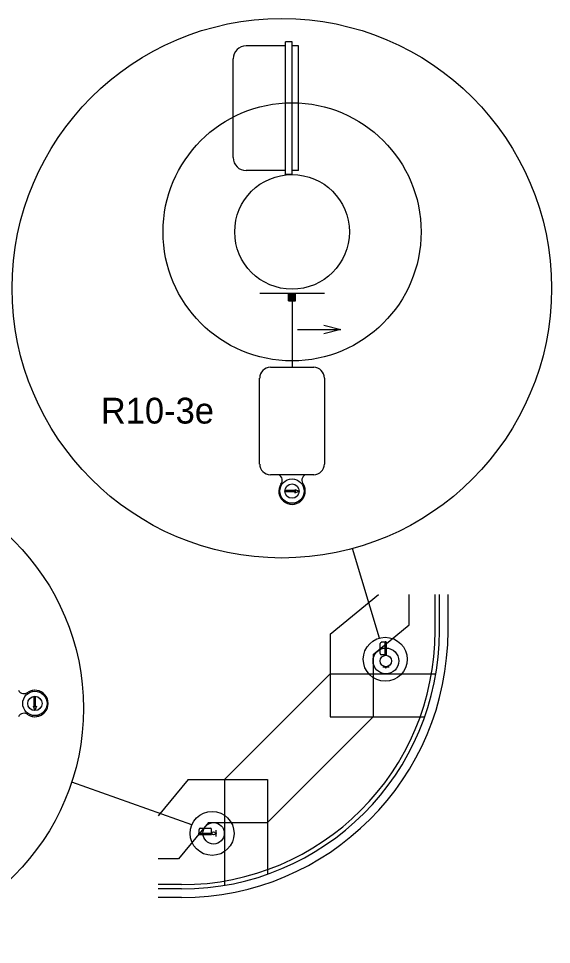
# Model space of a CAD drawing. Extents: x 418532 to 420296, y -565948 to -565286.
# Drawn here: x 419692.3 to 419785.2, y -565790.4 to -565629 of the extents above; entities that cross this region are included whole.
import ezdxf

# ---------------------------------------------------------------- set-up
doc = ezdxf.new("R2010")
doc.units = 0
doc.layers.add('T_Drafting', color=7, linetype='Continuous')

msp = doc.modelspace()

# ---------------------------------------------------------------- linework, layer by layer
at = {"layer": 'T_Drafting'}
for p, q in [((419738.87, -565656.2), (419738.87, -565633.07)), ((419739.99, -565633.07), (419738.87, -565633.07)), ((419739.99, -565656.2), (419739.99, -565633.07)), ((419738.87, -565633.76), (419731.99, -565633.76)), ((419741.12, -565633.76), (419739.99, -565633.76)), ((419741.12, -565655.51), (419741.12, -565633.76)), ((419729.74, -565653.26), (419729.74, -565636.01)), ((419738.87, -565655.51), (419731.99, -565655.51)), ((419741.12, -565655.51), (419739.99, -565655.51)), ((419739.99, -565656.2), (419738.87, -565656.2)), ((419745.62, -565676.95), (419734.37, -565676.95)), ((419739.37, -565678.2), (419739.37, -565676.95)), ((419739.37, -565678.19), (419740.61, -565676.95)), ((419739.37, -565678.17), (419740.59, -565676.95)), ((419739.37, -565678.14), (419740.57, -565676.95)), ((419739.37, -565678.12), (419740.55, -565676.95)), ((419739.37, -565678.1), (419740.52, -565676.95)), ((419739.37, -565678.08), (419740.5, -565676.95)), ((419739.37, -565678.06), (419740.48, -565676.95)), ((419739.37, -565678.04), (419740.46, -565676.95)), ((419739.37, -565678.02), (419740.44, -565676.95)), ((419739.37, -565678), (419740.42, -565676.95)), ((419739.37, -565677.98), (419740.4, -565676.95)), ((419739.37, -565677.95), (419740.38, -565676.95)), ((419739.37, -565677.93), (419740.35, -565676.95)), ((419739.37, -565677.91), (419740.33, -565676.95)), ((419739.37, -565677.89), (419740.31, -565676.95)), ((419739.37, -565677.87), (419740.29, -565676.95)), ((419739.37, -565677.85), (419740.27, -565676.95)), ((419739.37, -565677.83), (419740.25, -565676.95)), ((419739.37, -565677.81), (419740.23, -565676.95)), ((419739.37, -565677.78), (419740.21, -565676.95)), ((419739.37, -565677.76), (419740.19, -565676.95)), ((419739.37, -565677.74), (419740.16, -565676.95)), ((419739.37, -565677.72), (419740.14, -565676.95)), ((419739.37, -565677.7), (419740.12, -565676.95)), ((419739.37, -565677.68), (419740.1, -565676.95)), ((419739.37, -565677.66), (419740.08, -565676.95)), ((419739.37, -565677.64), (419740.06, -565676.95)), ((419739.37, -565677.61), (419740.04, -565676.95)), ((419739.37, -565677.59), (419740.02, -565676.95)), ((419739.37, -565677.57), (419739.99, -565676.95)), ((419739.37, -565677.55), (419739.97, -565676.95)), ((419739.37, -565677.53), (419739.95, -565676.95)), ((419739.37, -565677.51), (419739.93, -565676.95)), ((419739.37, -565677.49), (419739.91, -565676.95)), ((419739.37, -565677.47), (419739.89, -565676.95)), ((419739.37, -565677.44), (419739.87, -565676.95)), ((419739.37, -565677.42), (419739.85, -565676.95)), ((419739.37, -565677.4), (419739.82, -565676.95)), ((419739.37, -565677.38), (419739.8, -565676.95)), ((419739.37, -565677.36), (419739.78, -565676.95)), ((419739.37, -565677.34), (419739.76, -565676.95)), ((419739.37, -565677.32), (419739.74, -565676.95)), ((419739.37, -565677.3), (419739.72, -565676.95)), ((419739.37, -565677.28), (419739.7, -565676.95)), ((419739.37, -565677.25), (419739.68, -565676.95)), ((419739.37, -565677.23), (419739.65, -565676.95)), ((419739.37, -565677.21), (419739.63, -565676.95)), ((419739.37, -565677.19), (419739.61, -565676.95)), ((419739.37, -565677.17), (419739.59, -565676.95)), ((419739.37, -565677.15), (419739.57, -565676.95)), ((419739.37, -565677.13), (419739.55, -565676.95)), ((419739.37, -565677.11), (419739.53, -565676.95)), ((419739.37, -565677.08), (419739.51, -565676.95)), ((419739.37, -565677.06), (419739.49, -565676.95)), ((419739.37, -565677.04), (419739.46, -565676.95)), ((419739.37, -565677.02), (419739.44, -565676.95)), ((419739.37, -565677), (419739.42, -565676.95)), ((419739.37, -565676.98), (419739.4, -565676.95)), ((419739.37, -565676.96), (419739.38, -565676.95)), ((419739.38, -565678.2), (419740.62, -565676.96)), ((419739.4, -565678.2), (419740.62, -565676.98)), ((419739.42, -565678.2), (419740.62, -565677)), ((419739.44, -565678.2), (419740.62, -565677.02)), ((419739.47, -565678.2), (419740.62, -565677.04)), ((419739.49, -565678.2), (419740.62, -565677.06)), ((419739.51, -565678.2), (419740.62, -565677.09)), ((419739.53, -565678.2), (419740.62, -565677.11)), ((419739.55, -565678.2), (419740.62, -565677.13)), ((419740.62, -565678.2), (419740.62, -565676.95)), ((419739.37, -565678.2), (419740.62, -565678.2)), ((419739.57, -565678.2), (419740.62, -565677.15)), ((419739.59, -565678.2), (419740.62, -565677.17)), ((419739.61, -565678.2), (419740.62, -565677.19)), ((419739.64, -565678.2), (419740.62, -565677.21)), ((419739.66, -565678.2), (419740.62, -565677.23)), ((419739.68, -565678.2), (419740.62, -565677.26)), ((419739.7, -565678.2), (419740.62, -565677.28)), ((419739.72, -565678.2), (419740.62, -565677.3)), ((419739.74, -565678.2), (419740.62, -565677.32)), ((419739.76, -565678.2), (419740.62, -565677.34)), ((419739.78, -565678.2), (419740.62, -565677.36)), ((419739.8, -565678.2), (419740.62, -565677.38)), ((419739.83, -565678.2), (419740.62, -565677.4)), ((419739.85, -565678.2), (419740.62, -565677.43)), ((419739.87, -565678.2), (419740.62, -565677.45)), ((419739.89, -565678.2), (419740.62, -565677.47)), ((419739.91, -565678.2), (419740.62, -565677.49)), ((419739.93, -565678.2), (419740.62, -565677.51)), ((419739.95, -565678.2), (419740.62, -565677.53)), ((419739.97, -565678.2), (419740.62, -565677.55)), ((419739.99, -565678.2), (419739.99, -565689.8)), ((419740, -565678.2), (419740.62, -565677.57)), ((419740.02, -565678.2), (419740.62, -565677.59)), ((419740.04, -565678.2), (419740.62, -565677.62)), ((419740.06, -565678.2), (419740.62, -565677.64)), ((419740.08, -565678.2), (419740.62, -565677.66)), ((419740.1, -565678.2), (419740.62, -565677.68)), ((419740.12, -565678.2), (419740.62, -565677.7)), ((419740.14, -565678.2), (419740.62, -565677.72)), ((419740.17, -565678.2), (419740.62, -565677.74)), ((419740.19, -565678.2), (419740.62, -565677.76)), ((419740.21, -565678.2), (419740.62, -565677.79)), ((419740.23, -565678.2), (419740.62, -565677.81)), ((419740.25, -565678.2), (419740.62, -565677.83)), ((419740.27, -565678.2), (419740.62, -565677.85)), ((419740.29, -565678.2), (419740.62, -565677.87)), ((419740.31, -565678.2), (419740.62, -565677.89)), ((419740.34, -565678.2), (419740.62, -565677.91)), ((419740.36, -565678.2), (419740.62, -565677.93)), ((419740.38, -565678.2), (419740.62, -565677.96)), ((419740.4, -565678.2), (419740.62, -565677.98)), ((419740.42, -565678.2), (419740.62, -565678)), ((419740.44, -565678.2), (419740.62, -565678.02)), ((419740.46, -565678.2), (419740.62, -565678.04)), ((419740.48, -565678.2), (419740.62, -565678.06)), ((419740.5, -565678.2), (419740.62, -565678.08)), ((419740.53, -565678.2), (419740.62, -565678.1)), ((419740.55, -565678.2), (419740.62, -565678.13)), ((419740.57, -565678.2), (419740.62, -565678.15)), ((419740.59, -565678.2), (419740.62, -565678.17)), ((419740.61, -565678.2), (419740.62, -565678.19)), ((419740.96, -565683.2), (419748.51, -565683.2)), ((419736.22, -565689.8), (419743.77, -565689.8)), ((419734.34, -565706.68), (419734.34, -565691.68)), ((419745.64, -565691.68), (419745.64, -565706.68)), ((419743.77, -565708.55), (419736.22, -565708.55)), ((419738.75, -565711.29), (419738.75, -565711.51)), ((419740.63, -565711.29), (419738.75, -565711.29)), ((419740.63, -565711.51), (419738.75, -565711.51)), ((419740.48, -565711.1), (419741.24, -565711.4)), ((419740.63, -565711.29), (419740.48, -565711.1)), ((419740.48, -565711.7), (419741.24, -565711.4)), ((419740.48, -565711.7), (419740.63, -565711.51)), ((419755.22, -565737.02), (419750.51, -565721.42)), ((419746.61, -565736.36), (419755.07, -565729.41)), ((419760.44, -565734.71), (419760.44, -565729.41)), ((419764.94, -565735.76), (419764.94, -565729.41)), ((419765.69, -565735.76), (419765.69, -565729.41)), ((419767.19, -565735.76), (419767.19, -565729.41)), ((419754.11, -565739.91), (419760.44, -565734.71)), ((419746.61, -565736.36), (419746.61, -565750.76)), ((419755.34, -565739.71), (419755.34, -565737.99)), ((419756.25, -565737.76), (419755.56, -565737.76)), ((419756.25, -565740.01), (419756.25, -565737.69)), ((419756.36, -565737.69), (419756.25, -565737.69)), ((419756.36, -565740.01), (419756.36, -565737.69)), ((419756.48, -565737.76), (419756.36, -565737.76)), ((419756.48, -565739.94), (419756.48, -565737.76)), ((419754.11, -565739.91), (419754.11, -565750.76)), ((419756.25, -565739.94), (419755.56, -565739.94)), ((419756.36, -565740.01), (419756.25, -565740.01)), ((419756.48, -565739.94), (419756.36, -565739.94)), ((419746.61, -565743.26), (419728.19, -565761.68)), ((419746.61, -565743.26), (419765.06, -565743.26)), ((419756.93, -565742.08), (419755.8, -565742.08)), ((419756.3, -565742.21), (419756.3, -565742.08)), ((419756.3, -565742.21), (419756.43, -565742.08)), ((419756.3, -565742.21), (419756.43, -565742.08)), ((419756.3, -565742.2), (419756.43, -565742.08)), ((419756.3, -565742.2), (419756.42, -565742.08)), ((419756.3, -565742.2), (419756.42, -565742.08)), ((419756.3, -565742.2), (419756.42, -565742.08)), ((419756.3, -565742.2), (419756.42, -565742.08)), ((419756.3, -565742.19), (419756.41, -565742.08)), ((419756.3, -565742.19), (419756.41, -565742.08)), ((419756.3, -565742.19), (419756.41, -565742.08)), ((419756.3, -565742.19), (419756.41, -565742.08)), ((419756.3, -565742.19), (419756.41, -565742.08)), ((419756.3, -565742.18), (419756.4, -565742.08)), ((419756.3, -565742.18), (419756.4, -565742.08)), ((419756.3, -565742.18), (419756.4, -565742.08)), ((419756.3, -565742.18), (419756.4, -565742.08)), ((419756.3, -565742.17), (419756.4, -565742.08)), ((419756.3, -565742.17), (419756.39, -565742.08)), ((419756.3, -565742.17), (419756.39, -565742.08)), ((419756.3, -565742.17), (419756.39, -565742.08)), ((419756.3, -565742.17), (419756.39, -565742.08)), ((419756.3, -565742.16), (419756.39, -565742.08)), ((419756.3, -565742.16), (419756.38, -565742.08)), ((419756.3, -565742.16), (419756.38, -565742.08)), ((419756.3, -565742.16), (419756.38, -565742.08)), ((419756.3, -565742.16), (419756.38, -565742.08)), ((419756.3, -565742.15), (419756.37, -565742.08)), ((419756.3, -565742.15), (419756.37, -565742.08)), ((419756.3, -565742.15), (419756.37, -565742.08)), ((419756.3, -565742.15), (419756.37, -565742.08)), ((419756.3, -565742.14), (419756.37, -565742.08)), ((419756.3, -565742.14), (419756.36, -565742.08)), ((419756.3, -565742.14), (419756.36, -565742.08)), ((419756.3, -565742.14), (419756.36, -565742.08)), ((419756.3, -565742.14), (419756.36, -565742.08)), ((419756.3, -565742.13), (419756.36, -565742.08)), ((419756.3, -565742.13), (419756.35, -565742.08)), ((419756.3, -565742.13), (419756.35, -565742.08)), ((419756.3, -565742.13), (419756.35, -565742.08)), ((419756.3, -565742.13), (419756.35, -565742.08)), ((419756.3, -565742.12), (419756.34, -565742.08)), ((419756.3, -565742.12), (419756.34, -565742.08)), ((419756.3, -565742.12), (419756.34, -565742.08)), ((419756.3, -565742.12), (419756.34, -565742.08)), ((419756.3, -565742.12), (419756.34, -565742.08)), ((419756.3, -565742.11), (419756.33, -565742.08)), ((419756.3, -565742.11), (419756.33, -565742.08)), ((419756.3, -565742.11), (419756.33, -565742.08)), ((419756.3, -565742.11), (419756.33, -565742.08)), ((419756.3, -565742.1), (419756.33, -565742.08)), ((419756.3, -565742.1), (419756.32, -565742.08)), ((419756.3, -565742.1), (419756.32, -565742.08)), ((419756.3, -565742.1), (419756.32, -565742.08)), ((419756.3, -565742.1), (419756.32, -565742.08)), ((419756.3, -565742.09), (419756.32, -565742.08)), ((419756.3, -565742.09), (419756.31, -565742.08)), ((419756.3, -565742.09), (419756.31, -565742.08)), ((419756.3, -565742.09), (419756.31, -565742.08)), ((419756.3, -565742.09), (419756.31, -565742.08)), ((419756.3, -565742.08), (419756.3, -565742.08)), ((419756.3, -565742.08), (419756.3, -565742.08)), ((419756.3, -565742.21), (419756.43, -565742.21)), ((419756.31, -565742.21), (419756.43, -565742.09)), ((419756.31, -565742.21), (419756.43, -565742.09)), ((419756.31, -565742.21), (419756.43, -565742.09)), ((419756.31, -565742.21), (419756.43, -565742.09)), ((419756.32, -565742.21), (419756.43, -565742.09)), ((419756.32, -565742.21), (419756.43, -565742.1)), ((419756.32, -565742.21), (419756.43, -565742.1)), ((419756.32, -565742.21), (419756.43, -565742.1)), ((419756.32, -565742.21), (419756.43, -565742.1)), ((419756.33, -565742.21), (419756.43, -565742.1)), ((419756.33, -565742.21), (419756.43, -565742.11)), ((419756.33, -565742.21), (419756.43, -565742.11)), ((419756.33, -565742.21), (419756.43, -565742.11)), ((419756.33, -565742.21), (419756.43, -565742.11)), ((419756.34, -565742.21), (419756.43, -565742.12)), ((419756.34, -565742.21), (419756.43, -565742.12)), ((419756.34, -565742.21), (419756.43, -565742.12)), ((419756.34, -565742.21), (419756.43, -565742.12)), ((419756.35, -565742.21), (419756.43, -565742.12)), ((419756.35, -565742.21), (419756.43, -565742.13)), ((419756.35, -565742.21), (419756.43, -565742.13)), ((419756.35, -565742.21), (419756.43, -565742.13)), ((419756.35, -565742.21), (419756.43, -565742.13)), ((419756.36, -565742.21), (419756.43, -565742.13)), ((419756.36, -565742.21), (419756.43, -565742.14)), ((419756.36, -565742.21), (419756.43, -565742.14)), ((419756.36, -565742.21), (419756.43, -565742.14)), ((419756.36, -565742.21), (419756.43, -565742.14)), ((419756.37, -565742.21), (419756.43, -565742.14)), ((419756.37, -565742.21), (419756.43, -565742.15)), ((419756.37, -565742.21), (419756.43, -565742.15)), ((419756.37, -565742.21), (419756.43, -565742.15)), ((419756.37, -565742.21), (419756.43, -565742.15)), ((419756.38, -565742.21), (419756.43, -565742.16)), ((419756.38, -565742.21), (419756.43, -565742.16)), ((419756.38, -565742.21), (419756.43, -565742.16)), ((419756.38, -565742.21), (419756.43, -565742.16)), ((419756.39, -565742.21), (419756.43, -565742.16)), ((419756.39, -565742.21), (419756.43, -565742.17)), ((419756.39, -565742.21), (419756.43, -565742.17)), ((419756.39, -565742.21), (419756.43, -565742.17)), ((419756.39, -565742.21), (419756.43, -565742.17)), ((419756.4, -565742.21), (419756.43, -565742.17)), ((419756.4, -565742.21), (419756.43, -565742.18)), ((419756.4, -565742.21), (419756.43, -565742.18)), ((419756.4, -565742.21), (419756.43, -565742.18)), ((419756.4, -565742.21), (419756.43, -565742.18)), ((419756.41, -565742.21), (419756.43, -565742.19)), ((419756.41, -565742.21), (419756.43, -565742.19)), ((419756.41, -565742.21), (419756.43, -565742.19)), ((419756.41, -565742.21), (419756.43, -565742.19)), ((419756.42, -565742.21), (419756.43, -565742.19)), ((419756.42, -565742.21), (419756.43, -565742.2)), ((419756.42, -565742.21), (419756.43, -565742.2)), ((419756.42, -565742.21), (419756.43, -565742.2)), ((419756.42, -565742.21), (419756.43, -565742.2)), ((419756.43, -565742.21), (419756.43, -565742.08)), ((419756.43, -565742.21), (419756.43, -565742.2)), ((419695.02, -565747.18), (419695.25, -565747.18)), ((419695.02, -565749.06), (419695.02, -565747.18)), ((419695.25, -565749.06), (419695.25, -565747.18)), ((419694.84, -565748.91), (419695.14, -565749.67)), ((419695.02, -565749.06), (419694.84, -565748.91)), ((419695.44, -565748.91), (419695.14, -565749.67)), ((419695.44, -565748.91), (419695.25, -565749.06)), ((419754.11, -565750.76), (419735.69, -565769.18)), ((419746.61, -565750.76), (419763.11, -565750.76)), ((419722.52, -565769.61), (419701.56, -565762.14)), ((419721.85, -565761.68), (419716.65, -565768.01)), ((419721.85, -565761.68), (419735.69, -565761.68)), ((419728.19, -565761.68), (419728.19, -565780.13)), ((419735.69, -565761.68), (419735.69, -565778.18)), ((419725.39, -565769.18), (419720.19, -565775.51)), ((419723.79, -565771.06), (419723.79, -565770.37)), ((419724.01, -565770.14), (419725.74, -565770.14)), ((419725.39, -565769.18), (419735.69, -565769.18)), ((419725.96, -565771.06), (419725.96, -565770.37)), ((419726.67, -565770.49), (419726.67, -565771.62)), ((419723.72, -565771.06), (419726.03, -565771.06)), ((419723.72, -565771.17), (419723.72, -565771.06)), ((419723.72, -565771.17), (419726.03, -565771.17)), ((419723.79, -565771.28), (419723.79, -565771.17)), ((419723.79, -565771.28), (419725.96, -565771.28)), ((419725.96, -565771.28), (419725.96, -565771.17)), ((419726.03, -565771.17), (419726.03, -565771.06)), ((419726.79, -565770.99), (419726.67, -565770.99)), ((419726.67, -565771.12), (419726.79, -565770.99)), ((419726.67, -565771.12), (419726.79, -565770.99)), ((419726.67, -565771.11), (419726.79, -565770.99)), ((419726.67, -565771.11), (419726.79, -565770.99)), ((419726.67, -565771.11), (419726.78, -565770.99)), ((419726.67, -565771.11), (419726.78, -565770.99)), ((419726.67, -565771.11), (419726.78, -565770.99)), ((419726.67, -565771.1), (419726.78, -565770.99)), ((419726.67, -565771.1), (419726.78, -565770.99)), ((419726.67, -565771.1), (419726.77, -565770.99)), ((419726.67, -565771.1), (419726.77, -565770.99)), ((419726.67, -565771.1), (419726.77, -565770.99)), ((419726.67, -565771.09), (419726.77, -565770.99)), ((419726.67, -565771.09), (419726.77, -565770.99)), ((419726.67, -565771.09), (419726.76, -565770.99)), ((419726.67, -565771.09), (419726.76, -565770.99)), ((419726.67, -565771.08), (419726.76, -565770.99)), ((419726.67, -565771.08), (419726.76, -565770.99)), ((419726.67, -565771.08), (419726.76, -565770.99)), ((419726.67, -565771.08), (419726.75, -565770.99)), ((419726.67, -565771.08), (419726.75, -565770.99)), ((419726.67, -565771.07), (419726.75, -565770.99)), ((419726.67, -565771.07), (419726.75, -565770.99)), ((419726.67, -565771.07), (419726.74, -565770.99)), ((419726.67, -565771.07), (419726.74, -565770.99)), ((419726.67, -565771.07), (419726.74, -565770.99)), ((419726.67, -565771.06), (419726.74, -565770.99)), ((419726.67, -565771.06), (419726.74, -565770.99)), ((419726.67, -565771.06), (419726.73, -565770.99)), ((419726.67, -565771.06), (419726.73, -565770.99)), ((419726.67, -565771.05), (419726.73, -565770.99)), ((419726.67, -565771.05), (419726.73, -565770.99)), ((419726.67, -565771.05), (419726.73, -565770.99)), ((419726.67, -565771.05), (419726.72, -565770.99)), ((419726.67, -565771.05), (419726.72, -565770.99)), ((419726.67, -565771.04), (419726.72, -565770.99)), ((419726.67, -565771.04), (419726.72, -565770.99)), ((419726.67, -565771.04), (419726.71, -565770.99)), ((419726.67, -565771.04), (419726.71, -565770.99)), ((419726.67, -565771.04), (419726.71, -565770.99)), ((419726.67, -565771.03), (419726.71, -565770.99)), ((419726.67, -565771.03), (419726.71, -565770.99)), ((419726.67, -565771.03), (419726.7, -565770.99)), ((419726.67, -565771.03), (419726.7, -565770.99)), ((419726.67, -565771.03), (419726.7, -565770.99)), ((419726.67, -565771.02), (419726.7, -565770.99)), ((419726.67, -565771.02), (419726.7, -565770.99)), ((419726.67, -565771.02), (419726.69, -565770.99)), ((419726.67, -565771.02), (419726.69, -565770.99)), ((419726.67, -565771.01), (419726.69, -565770.99)), ((419726.67, -565771.01), (419726.69, -565770.99)), ((419726.67, -565771.01), (419726.69, -565770.99)), ((419726.67, -565771.01), (419726.68, -565770.99)), ((419726.67, -565771.01), (419726.68, -565770.99)), ((419726.67, -565771), (419726.68, -565770.99)), ((419726.67, -565771), (419726.68, -565770.99)), ((419726.67, -565771), (419726.67, -565770.99)), ((419726.67, -565771), (419726.67, -565770.99)), ((419726.67, -565771), (419726.67, -565770.99)), ((419726.67, -565771.12), (419726.79, -565771)), ((419726.67, -565771.12), (419726.79, -565771)), ((419726.67, -565771.12), (419726.79, -565771)), ((419726.79, -565771.12), (419726.67, -565771.12)), ((419726.68, -565771.12), (419726.79, -565771)), ((419726.68, -565771.12), (419726.79, -565771)), ((419726.68, -565771.12), (419726.79, -565771.01)), ((419726.68, -565771.12), (419726.79, -565771.01)), ((419726.69, -565771.12), (419726.79, -565771.01)), ((419726.69, -565771.12), (419726.79, -565771.01)), ((419726.69, -565771.12), (419726.79, -565771.01)), ((419726.69, -565771.12), (419726.79, -565771.02)), ((419726.69, -565771.12), (419726.79, -565771.02)), ((419726.7, -565771.12), (419726.79, -565771.02)), ((419726.7, -565771.12), (419726.79, -565771.02)), ((419726.7, -565771.12), (419726.79, -565771.03)), ((419726.7, -565771.12), (419726.79, -565771.03)), ((419726.7, -565771.12), (419726.79, -565771.03)), ((419726.71, -565771.12), (419726.79, -565771.03)), ((419726.71, -565771.12), (419726.79, -565771.03)), ((419726.71, -565771.12), (419726.79, -565771.04)), ((419726.71, -565771.12), (419726.79, -565771.04)), ((419726.72, -565771.12), (419726.79, -565771.04)), ((419726.72, -565771.12), (419726.79, -565771.04)), ((419726.72, -565771.12), (419726.79, -565771.04)), ((419726.72, -565771.12), (419726.79, -565771.05)), ((419726.72, -565771.12), (419726.79, -565771.05)), ((419726.73, -565771.12), (419726.79, -565771.05)), ((419726.73, -565771.12), (419726.79, -565771.05)), ((419726.73, -565771.12), (419726.79, -565771.06)), ((419726.73, -565771.12), (419726.79, -565771.06)), ((419726.73, -565771.12), (419726.79, -565771.06)), ((419726.74, -565771.12), (419726.79, -565771.06)), ((419726.74, -565771.12), (419726.79, -565771.06)), ((419726.74, -565771.12), (419726.79, -565771.07)), ((419726.74, -565771.12), (419726.79, -565771.07)), ((419726.74, -565771.12), (419726.79, -565771.07)), ((419726.75, -565771.12), (419726.79, -565771.07)), ((419726.75, -565771.12), (419726.79, -565771.07)), ((419726.75, -565771.12), (419726.79, -565771.08)), ((419726.75, -565771.12), (419726.79, -565771.08)), ((419726.76, -565771.12), (419726.79, -565771.08)), ((419726.76, -565771.12), (419726.79, -565771.08)), ((419726.76, -565771.12), (419726.79, -565771.08)), ((419726.76, -565771.12), (419726.79, -565771.09)), ((419726.76, -565771.12), (419726.79, -565771.09)), ((419726.77, -565771.12), (419726.79, -565771.09)), ((419726.77, -565771.12), (419726.79, -565771.09)), ((419726.77, -565771.12), (419726.79, -565771.1)), ((419726.77, -565771.12), (419726.79, -565771.1)), ((419726.77, -565771.12), (419726.79, -565771.1)), ((419726.78, -565771.12), (419726.79, -565771.1)), ((419726.78, -565771.12), (419726.79, -565771.1)), ((419726.78, -565771.12), (419726.79, -565771.11)), ((419726.78, -565771.12), (419726.79, -565771.11)), ((419726.79, -565771.12), (419726.79, -565770.99)), ((419726.79, -565771.12), (419726.79, -565771.11)), ((419726.79, -565771.12), (419726.79, -565771.11)), ((419726.79, -565771.12), (419726.79, -565771.11)), ((419726.79, -565771.12), (419726.79, -565771.12)), ((419726.79, -565771.12), (419726.79, -565771.12)), ((419720.19, -565775.51), (419716.65, -565775.51)), ((419720.69, -565780.01), (419716.65, -565780.01)), ((419720.69, -565780.76), (419716.65, -565780.76)), ((419720.69, -565782.26), (419716.65, -565782.26))]:
    msp.add_line(p, q, dxfattribs=at)
msp.add_lwpolyline([(419745.51, -565682.45), (419748.51, -565683.2), (419745.51, -565683.95)], dxfattribs=at)
for centre, radius in [((419738.21, -565676.03), 47.03), ((419739.99, -565666.2), 22.5), ((419739.99, -565666.2), 10), ((419662.46, -565749.28), 41.16), ((419739.99, -565711.4), 2.12), ((419739.99, -565711.4), 1.25), ((419756.24, -565740.71), 3.83), ((419756.36, -565741.01), 2.25), ((419756.36, -565741.01), 1), ((419695.14, -565748.42), 2.12), ((419695.14, -565748.42), 1.25), ((419726.05, -565771.08), 3.83), ((419726.31, -565771.06), 1.87), ((419726.31, -565771.06), 0.281)]:
    msp.add_circle(centre, radius, dxfattribs=at)
for centre, radius, start, end in [((419731.99, -565636.01), 2.25, 90, 180), ((419731.99, -565653.26), 2.25, 180, 270), ((419736.22, -565691.68), 1.87, 90, 180), ((419743.77, -565691.68), 1.87, 0, 90), ((419736.22, -565706.68), 1.87, 180, 270), ((419743.77, -565706.68), 1.87, 270, 0), ((419737.23, -565709.5), 1.05, 318.1972, 64.8044), ((419742.75, -565709.5), 1.05, 115.1956, 221.8028), ((419739.99, -565711.4), 2.31, 148.7402, 227.4934), ((419739.99, -565711.4), 2.31, 148.7402, 31.2598), ((419739.99, -565711.4), 2.31, 312.5066, 31.2598), ((419720.69, -565735.76), 45, 270, 0), ((419720.69, -565735.76), 46.5, 270, 0), ((419720.69, -565735.76), 44.25, 270, 0), ((419755.56, -565737.99), 0.225, 90, 180), ((419755.56, -565739.71), 0.225, 180, 270), ((419693.24, -565745.66), 1.05, 205.1956, 311.8028), ((419695.14, -565748.42), 2.31, 238.7402, 121.2598), ((419695.14, -565748.42), 2.31, 42.5066, 121.2598), ((419693.24, -565751.18), 1.05, 48.1972, 154.8044), ((419695.14, -565748.42), 2.31, 238.7402, 317.4934), ((419724.01, -565770.37), 0.225, 90, 180), ((419725.74, -565770.37), 0.225, 360, 90)]:
    msp.add_arc(centre, radius, start, end, dxfattribs=at)

# ---------------------------------------------------------------- texts
msp.add_text('R10-3e', height=4.5, dxfattribs=at).set_placement((419706.64, -565699.62))

doc.saveas('drawing.dxf')
